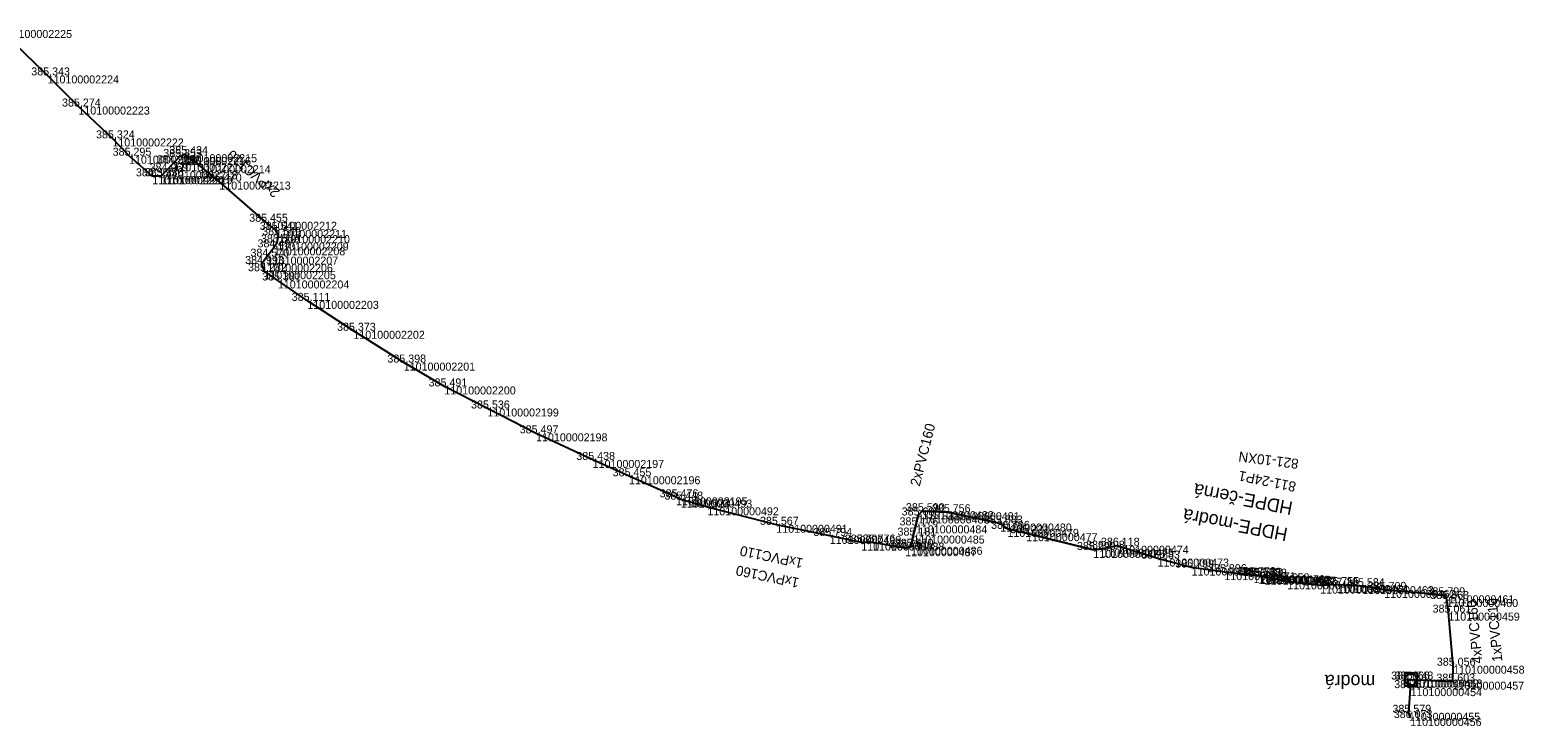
# Model space of a CAD drawing. Extents: x -724084 to -720954, y -948423 to -945131.
# Drawn here: x -721178.5 to -720954.4, y -948422.5 to -948318.1 of the extents above; entities that cross this region are included whole.
import ezdxf

# ---------------------------------------------------------------- set-up
doc = ezdxf.new("R2010")
doc.units = 0
for name, color, linetype in [('Vrstva 28', 7, 'Continuous'), ('Vrstva 31', 7, 'Continuous'), ('Vrstva 33', 7, 'Continuous'), ('Vrstva 35', 7, 'Continuous'), ('Vrstva 60', 7, 'Continuous'), ('Vrstva 61', 7, 'Continuous')]:
    doc.layers.add(name, color=color, linetype=linetype)

msp = doc.modelspace()

# ---------------------------------------------------------------- linework, layer by layer
at = {"layer": 'Vrstva 28'}
for points in [[(-721017.64, -948395.91), (-721019.02, -948396.1), (-721029.09, -948393.58), (-721031.89, -948392.93), (-721032.96, -948392.13), (-721040.78, -948390.44), (-721044.67, -948390.28), (-721045.3, -948390.92), (-721045.63, -948392.41), (-721046.02, -948393.94), (-721046.35, -948395.62), (-721047.24, -948395.83), (-721052.06, -948394.98), (-721053.83, -948394.99), (-721058.55, -948393.99), (-721066.56, -948392.32), (-721076.9, -948389.7), (-721080.89, -948388.54), (-721081.6, -948388.2), (-721088.66, -948385.04), (-721094.11, -948382.59), (-721102.6, -948378.6), (-721109.9, -948374.87), (-721116.36, -948371.56), (-721122.45, -948367.98), (-721130, -948363.21), (-721136.9, -948358.72), (-721141.33, -948355.66), (-721143.35, -948354.27), (-721143.79, -948353.18), (-721142.99, -948352.08), (-721141.93, -948350.69), (-721141.42, -948349.96), (-721141.23, -948348.86), (-721141.68, -948348.07), (-721143.18, -948346.85), (-721150.11, -948340.82), (-721153.11, -948338.36), (-721155.16, -948336.71), (-721156.07, -948337.13), (-721157, -948338.07), (-721158.11, -948339.27), (-721158.84, -948340.01), (-721160.16, -948340.03), (-721163.65, -948336.94), (-721166.15, -948334.34), (-721171.25, -948329.56), (-721175.87, -948324.89), (-721182.91, -948318.07)], [(-720966.59, -948402.9), (-720975.39, -948402.09), (-720978.66, -948401.53), (-720982.49, -948401.35), (-720984.99, -948401.45), (-720989.94, -948400.81), (-720993.33, -948400.12), (-720993.99, -948399.99), (-720994.27, -948399.98), (-720994.99, -948399.88), (-720999.36, -948399.43), (-721004.27, -948398.73), (-721009.38, -948397.39), (-721015.42, -948395.46), (-721017.64, -948395.91)], [(-720965.1, -948415.86), (-720965.04, -948413.47), (-720965.76, -948405.5), (-720966.01, -948403.46), (-720966.59, -948402.9)], [(-720971.49, -948421.32), (-720971.69, -948420.53), (-720971.43, -948416.83), (-720971.89, -948415.54), (-720971.36, -948415.54), (-720965.1, -948415.86)]]:
    msp.add_lwpolyline(points, dxfattribs=at)
at = {"layer": 'Vrstva 31'}
for points in [[(-721017.64, -948395.91), (-721019.02, -948396.1), (-721029.09, -948393.58), (-721031.89, -948392.93), (-721032.96, -948392.13), (-721040.78, -948390.44), (-721044.67, -948390.28), (-721045.3, -948390.92), (-721045.63, -948392.41), (-721046.02, -948393.94), (-721046.35, -948395.62), (-721047.24, -948395.83), (-721052.06, -948394.98), (-721053.83, -948394.99), (-721058.55, -948393.99), (-721066.56, -948392.32), (-721076.9, -948389.7), (-721080.89, -948388.54), (-721081.6, -948388.2), (-721088.66, -948385.04), (-721094.11, -948382.59), (-721102.6, -948378.6), (-721109.9, -948374.87), (-721116.36, -948371.56), (-721122.45, -948367.98), (-721130, -948363.21), (-721136.9, -948358.72), (-721141.33, -948355.66), (-721143.35, -948354.27), (-721143.79, -948353.18), (-721142.99, -948352.08), (-721141.93, -948350.69), (-721141.42, -948349.96), (-721141.23, -948348.86), (-721141.68, -948348.07), (-721143.18, -948346.85), (-721150.11, -948340.82), (-721153.11, -948338.36), (-721155.16, -948336.71), (-721156.07, -948337.13), (-721157, -948338.07), (-721158.11, -948339.27), (-721158.84, -948340.01), (-721160.16, -948340.03), (-721163.65, -948336.94), (-721166.15, -948334.34), (-721171.25, -948329.56), (-721175.87, -948324.89), (-721182.91, -948318.07)], [(-720966.59, -948402.9), (-720975.39, -948402.09), (-720978.66, -948401.53), (-720982.49, -948401.35), (-720984.99, -948401.45), (-720989.94, -948400.81), (-720993.33, -948400.12), (-720993.99, -948399.99), (-720994.27, -948399.98), (-720994.99, -948399.88), (-720999.36, -948399.43), (-721004.27, -948398.73), (-721009.38, -948397.39), (-721015.42, -948395.46), (-721017.64, -948395.91)], [(-720965.1, -948415.86), (-720965.04, -948413.47), (-720965.76, -948405.5), (-720966.01, -948403.46), (-720966.59, -948402.9)], [(-720971.49, -948421.32), (-720971.69, -948420.53), (-720971.43, -948416.83), (-720971.89, -948415.54), (-720971.36, -948415.54), (-720965.1, -948415.86)]]:
    msp.add_lwpolyline(points, dxfattribs=at)
at = {"layer": 'Vrstva 33'}
msp.add_lwpolyline([(-720971.49, -948421.32), (-720971.69, -948420.53), (-720971.43, -948416.83), (-720971.89, -948415.54), (-720971.36, -948415.54), (-720965.1, -948415.86), (-720965.04, -948413.47), (-720965.76, -948405.5), (-720966.01, -948403.46), (-720966.59, -948402.9), (-720975.39, -948402.09), (-720978.66, -948401.53), (-720982.49, -948401.35), (-720984.99, -948401.45), (-720989.94, -948400.81), (-720993.33, -948400.12), (-720993.99, -948399.99), (-720994.27, -948399.98), (-720994.99, -948399.88), (-720999.36, -948399.43), (-721004.27, -948398.73), (-721009.38, -948397.39), (-721015.42, -948395.46), (-721017.64, -948395.91), (-721019.02, -948396.1), (-721029.09, -948393.58), (-721031.89, -948392.93), (-721032.96, -948392.13), (-721040.78, -948390.44), (-721044.67, -948390.28), (-721045.3, -948390.92), (-721045.63, -948392.41), (-721046.02, -948393.94), (-721046.35, -948395.62), (-721047.24, -948395.83), (-721052.06, -948394.98), (-721053.83, -948394.99), (-721058.55, -948393.99), (-721066.56, -948392.32), (-721076.9, -948389.7), (-721080.89, -948388.54), (-721081.6, -948388.2), (-721088.66, -948385.04), (-721094.11, -948382.59), (-721102.6, -948378.6), (-721109.9, -948374.87), (-721116.36, -948371.56), (-721122.45, -948367.98), (-721130, -948363.21), (-721136.9, -948358.72), (-721141.33, -948355.66), (-721143.35, -948354.27), (-721143.79, -948353.18), (-721142.99, -948352.08), (-721141.93, -948350.69), (-721141.42, -948349.96), (-721141.23, -948348.86), (-721141.68, -948348.07), (-721143.18, -948346.85), (-721150.11, -948340.82), (-721153.11, -948338.36), (-721155.16, -948336.71), (-721156.07, -948337.13), (-721157, -948338.07), (-721158.11, -948339.27), (-721158.84, -948340.01), (-721160.16, -948340.03), (-721163.65, -948336.94), (-721166.15, -948334.34), (-721171.25, -948329.56), (-721175.87, -948324.89), (-721182.91, -948318.07)], dxfattribs=at)
msp.add_lwpolyline([(-720970.4, -948414.58), (-720972.32, -948414.58), (-720972.32, -948416.5), (-720970.4, -948416.5)], close=True, dxfattribs=at)
msp.add_circle((-720971.37, -948415.54), 0.864, dxfattribs=at)
at = {"layer": 'Vrstva 35'}
for points in [[(-721143.35, -948354.27), (-721143.79, -948353.18), (-721142.99, -948352.08), (-721141.93, -948350.69), (-721141.42, -948349.96), (-721141.23, -948348.86), (-721141.68, -948348.07), (-721143.18, -948346.85), (-721150.11, -948340.82), (-721153.11, -948338.36), (-721155.16, -948336.71), (-721156.07, -948337.13), (-721157, -948338.07), (-721158.11, -948339.27), (-721158.84, -948340.01), (-721160.16, -948340.03)], [(-721052.06, -948394.98), (-721053.83, -948394.99), (-721058.55, -948393.99), (-721066.56, -948392.32), (-721076.9, -948389.7), (-721080.89, -948388.54)], [(-721047.24, -948395.83), (-721046.35, -948395.62), (-721046.02, -948393.94), (-721045.63, -948392.41), (-721045.3, -948390.92), (-721044.67, -948390.28), (-721040.78, -948390.44), (-721032.96, -948392.13), (-721031.89, -948392.93), (-721029.09, -948393.58), (-721019.02, -948396.1), (-721017.64, -948395.91)], [(-720965.1, -948415.86), (-720965.04, -948413.47), (-720965.76, -948405.5), (-720966.01, -948403.46), (-720966.59, -948402.9)]]:
    msp.add_lwpolyline(points, dxfattribs=at)
at = {"layer": 'Vrstva 60'}
for p, q in [((-721175.87, -948324.89), (-721175.87, -948324.89)), ((-721171.25, -948329.56), (-721171.25, -948329.56)), ((-721166.15, -948334.34), (-721166.15, -948334.34)), ((-721163.65, -948336.94), (-721163.65, -948336.94)), ((-721156.07, -948337.13), (-721156.07, -948337.13)), ((-721155.16, -948336.71), (-721155.16, -948336.71)), ((-721158.11, -948339.27), (-721158.11, -948339.27)), ((-721157, -948338.07), (-721157, -948338.07)), ((-721153.11, -948338.36), (-721153.11, -948338.36)), ((-721160.16, -948340.03), (-721160.16, -948340.03)), ((-721158.84, -948340.01), (-721158.84, -948340.01)), ((-721150.11, -948340.82), (-721150.11, -948340.82)), ((-721143.18, -948346.85), (-721143.18, -948346.85)), ((-721141.68, -948348.07), (-721141.68, -948348.07)), ((-721141.93, -948350.69), (-721141.93, -948350.69)), ((-721141.42, -948349.96), (-721141.42, -948349.96)), ((-721141.23, -948348.86), (-721141.23, -948348.86)), ((-721142.99, -948352.08), (-721142.99, -948352.08)), ((-721143.79, -948353.18), (-721143.79, -948353.18)), ((-721143.35, -948354.27), (-721143.35, -948354.27)), ((-721141.33, -948355.66), (-721141.33, -948355.66)), ((-721136.9, -948358.72), (-721136.9, -948358.72)), ((-721130, -948363.21), (-721130, -948363.21)), ((-721122.45, -948367.98), (-721122.45, -948367.98)), ((-721116.36, -948371.56), (-721116.36, -948371.56)), ((-721109.9, -948374.87), (-721109.9, -948374.87)), ((-721102.6, -948378.6), (-721102.6, -948378.6)), ((-721094.11, -948382.59), (-721094.11, -948382.59)), ((-721088.66, -948385.04), (-721088.66, -948385.04)), ((-721081.6, -948388.2), (-721081.6, -948388.2)), ((-721080.89, -948388.54), (-721080.89, -948388.54)), ((-721076.9, -948389.7), (-721076.9, -948389.7)), ((-721045.3, -948390.92), (-721045.3, -948390.92)), ((-721044.67, -948390.28), (-721044.67, -948390.28)), ((-721040.78, -948390.44), (-721040.78, -948390.44)), ((-721066.56, -948392.32), (-721066.56, -948392.32)), ((-721045.63, -948392.41), (-721045.63, -948392.41)), ((-721032.96, -948392.13), (-721032.96, -948392.13)), ((-721031.89, -948392.93), (-721031.89, -948392.93)), ((-721058.55, -948393.99), (-721058.55, -948393.99)), ((-721053.83, -948394.99), (-721053.83, -948394.99)), ((-721052.06, -948394.98), (-721052.06, -948394.98)), ((-721046.35, -948395.62), (-721046.35, -948395.62)), ((-721046.02, -948393.94), (-721046.02, -948393.94)), ((-721029.09, -948393.58), (-721029.09, -948393.58)), ((-721015.42, -948395.46), (-721015.42, -948395.46)), ((-721047.24, -948395.83), (-721047.24, -948395.83)), ((-721019.02, -948396.1), (-721019.02, -948396.1)), ((-721017.64, -948395.91), (-721017.64, -948395.91)), ((-721009.38, -948397.39), (-721009.38, -948397.39)), ((-721004.27, -948398.73), (-721004.27, -948398.73)), ((-720999.36, -948399.43), (-720999.36, -948399.43)), ((-720994.99, -948399.88), (-720994.99, -948399.88)), ((-720994.27, -948399.98), (-720994.27, -948399.98)), ((-720993.99, -948399.99), (-720993.99, -948399.99)), ((-720993.33, -948400.12), (-720993.33, -948400.12)), ((-720989.94, -948400.81), (-720989.94, -948400.81)), ((-720984.99, -948401.45), (-720984.99, -948401.45)), ((-720982.49, -948401.35), (-720982.49, -948401.35)), ((-720978.66, -948401.53), (-720978.66, -948401.53)), ((-720975.39, -948402.09), (-720975.39, -948402.09)), ((-720966.59, -948402.9), (-720966.59, -948402.9)), ((-720966.01, -948403.46), (-720966.01, -948403.46)), ((-720965.76, -948405.5), (-720965.76, -948405.5)), ((-720965.04, -948413.47), (-720965.04, -948413.47)), ((-720971.89, -948415.54), (-720971.89, -948415.54)), ((-720971.36, -948415.54), (-720971.36, -948415.54)), ((-720971.43, -948416.83), (-720971.43, -948416.83)), ((-720965.1, -948415.86), (-720965.1, -948415.86)), ((-720971.69, -948420.53), (-720971.69, -948420.53)), ((-720971.49, -948421.32), (-720971.49, -948421.32))]:
    msp.add_line(p, q, dxfattribs=at)

# ---------------------------------------------------------------- texts
at = {"layer": 'Vrstva 28'}
msp.add_text('811-24P1', height=1.5, rotation=168.4498, dxfattribs=at).set_placement((-720988.52, -948385.94))
at = {"layer": 'Vrstva 31'}
msp.add_text('821-10XN', height=1.5, rotation=172.6697, dxfattribs=at).set_placement((-720988.16, -948382.47))
at = {"layer": 'Vrstva 33'}
for s, rotation, p in [('HDPE-černá', 169.188, (-720988.99, -948388.91)), ('HDPE-modrá', 169.188, (-720989.74, -948392.84)), ('modrá', 180, (-720976.72, -948414.84))]:
    msp.add_text(s, height=2, rotation=rotation, dxfattribs=at).set_placement(p)
at = {"layer": 'Vrstva 35'}
for s, rotation, p in [('2xPVC110', 138.9782, (-721140.91, -948342.24)), ('2xPVC160', 75.7968, (-721045.06, -948386.64)), ('1xPVC110', 168.2091, (-721062.44, -948397.41)), ('1xPVC160', 168.2091, (-721063.05, -948400.35)), ('4xPVC160', 95.1899, (-720960.64, -948413.09)), ('1xPVC110', 95.1899, (-720957.65, -948412.82))]:
    msp.add_text(s, height=1.5, rotation=rotation, dxfattribs=at).set_placement(p)
at = {"layer": 'Vrstva 60'}
for s, p in [('110100002225', (-721182.91, -948319.27)), ('110100002224', (-721175.87, -948326.09)), ('110100002223', (-721171.25, -948330.76)), ('110100002222', (-721166.15, -948335.55)), ('110100002221', (-721163.65, -948338.14)), ('110100002216', (-721156.07, -948338.33)), ('110100002215', (-721155.16, -948337.91)), ('110100002218', (-721158.11, -948340.47)), ('110100002217', (-721157, -948339.27)), ('110100002214', (-721153.11, -948339.56)), ('110100002220', (-721160.16, -948341.23)), ('110100002219', (-721158.84, -948341.21)), ('110100002213', (-721150.11, -948342.02)), ('110100002212', (-721143.18, -948348.05)), ('110100002211', (-721141.68, -948349.27)), ('110100002208', (-721141.93, -948351.89)), ('110100002209', (-721141.42, -948351.16)), ('110100002210', (-721141.23, -948350.06)), ('110100002207', (-721142.99, -948353.28)), ('110100002206', (-721143.79, -948354.38)), ('110100002205', (-721143.35, -948355.47)), ('110100002204', (-721141.33, -948356.86)), ('110100002203', (-721136.9, -948359.92)), ('110100002202', (-721130, -948364.41)), ('110100002201', (-721122.45, -948369.19)), ('110100002200', (-721116.36, -948372.76)), ('110100002199', (-721109.9, -948376.07)), ('110100002198', (-721102.6, -948379.8)), ('110100002197', (-721094.11, -948383.79)), ('110100002196', (-721088.66, -948386.24)), ('110100002195', (-721081.6, -948389.4)), ('110100000493', (-721080.89, -948389.74)), ('110100000492', (-721076.9, -948390.9)), ('110100000483', (-721045.3, -948392.12)), ('110100000482', (-721044.67, -948391.48)), ('110100000481', (-721040.78, -948391.64)), ('110100000491', (-721066.56, -948393.52)), ('110100000484', (-721045.63, -948393.61)), ('110100000480', (-721032.96, -948393.33)), ('110100000479', (-721031.89, -948394.13)), ('110100000490', (-721058.55, -948395.19)), ('110100000489', (-721053.83, -948396.19)), ('110100000488', (-721052.06, -948396.18)), ('110100000486', (-721046.35, -948396.82)), ('110100000485', (-721046.02, -948395.14)), ('110100000477', (-721029.09, -948394.78)), ('110100000474', (-721015.42, -948396.66)), ('110100000487', (-721047.24, -948397.03)), ('110100000476', (-721019.02, -948397.3)), ('110100000475', (-721017.64, -948397.11)), ('110100000473', (-721009.38, -948398.59)), ('110100000472', (-721004.27, -948399.93)), ('110100000471', (-720999.36, -948400.63)), ('110100000470', (-720994.99, -948401.08)), ('110100000469', (-720994.27, -948401.18)), ('110100000468', (-720993.99, -948401.19)), ('110100000467', (-720993.33, -948401.32)), ('110100000466', (-720989.94, -948402.01)), ('110100000465', (-720984.99, -948402.65)), ('110100000464', (-720982.49, -948402.55)), ('110100000463', (-720978.66, -948402.73)), ('110100000462', (-720975.39, -948403.29)), ('110100000461', (-720966.59, -948404.1)), ('110100000460', (-720966.01, -948404.66)), ('110100000459', (-720965.76, -948406.7)), ('110100000458', (-720965.04, -948414.67)), ('110100000452', (-720971.89, -948416.74)), ('110100000453', (-720971.36, -948416.74)), ('110100000454', (-720971.43, -948418.03)), ('110100000457', (-720965.1, -948417.06)), ('110100000455', (-720971.69, -948421.73)), ('110100000456', (-720971.49, -948422.52))]:
    msp.add_text(s, height=1.2, dxfattribs=at).set_placement(p)
at = {"layer": 'Vrstva 61'}
for s, p in [('385.343', (-721178.32, -948324.89)), ('385.274', (-721173.7, -948329.56)), ('385.324', (-721168.6, -948334.34)), ('385.295', (-721166.11, -948336.94)), ('384.968', (-721159.46, -948338.07)), ('385.353', (-721158.52, -948337.13)), ('385.434', (-721157.61, -948336.71)), ('385.398', (-721155.56, -948338.36)), ('385.355', (-721162.62, -948340.03)), ('385.330', (-721161.29, -948340.01)), ('384.969', (-721160.56, -948339.27)), ('385.470', (-721152.56, -948340.82)), ('385.455', (-721145.63, -948346.85)), ('385.541', (-721144.04, -948348.07)), ('385.549', (-721143.69, -948348.86)), ('384.497', (-721144.38, -948350.69)), ('385.509', (-721143.87, -948349.96)), ('384.993', (-721146.24, -948353.18)), ('384.570', (-721145.44, -948352.08)), ('385.282', (-721145.8, -948354.27)), ('385.381', (-721143.69, -948355.66)), ('385.111', (-721139.25, -948358.72)), ('385.373', (-721132.45, -948363.21)), ('385.398', (-721124.9, -948367.98)), ('385.491', (-721118.72, -948371.56)), ('385.536', (-721112.35, -948374.87)), ('385.497', (-721105.05, -948378.6)), ('385.438', (-721096.56, -948382.59)), ('385.455', (-721091.11, -948385.04)), ('385.476', (-721084.06, -948388.2)), ('385.448', (-721083.34, -948388.54)), ('385.523', (-721079.35, -948389.7)), ('385.567', (-721069.01, -948392.32)), ('385.688', (-721047.76, -948390.92)), ('385.590', (-721047.12, -948390.28)), ('385.756', (-721043.23, -948390.44)), ('385.883', (-721035.41, -948392.13)), ('385.794', (-721061, -948393.99)), ('385.181', (-721048.38, -948393.94)), ('385.176', (-721048.08, -948392.41)), ('385.706', (-721034.35, -948392.93)), ('385.231', (-721031.45, -948393.58)), ('385.795', (-721056.29, -948394.99)), ('385.776', (-721054.51, -948394.98)), ('385.761', (-721049.59, -948395.83)), ('385.570', (-721048.8, -948395.62)), ('385.290', (-721021.47, -948396.1)), ('386.198', (-721020.1, -948395.91)), ('386.118', (-721017.87, -948395.46)), ('385.883', (-721011.83, -948397.39)), ('385.799', (-721006.72, -948398.73)), ('385.806', (-721001.81, -948399.43)), ('385.773', (-720997.44, -948399.88)), ('385.588', (-720996.72, -948399.98)), ('385.583', (-720996.44, -948399.99)), ('385.738', (-720995.78, -948400.12)), ('385.658', (-720992.39, -948400.81)), ('385.737', (-720987.44, -948401.45)), ('385.755', (-720984.94, -948401.35)), ('385.584', (-720981.11, -948401.53)), ('385.709', (-720977.85, -948402.09)), ('385.799', (-720969.04, -948402.9)), ('385.868', (-720968.47, -948403.46)), ('385.061', (-720968.12, -948405.5)), ('385.056', (-720967.49, -948413.47)), ('385.666', (-720974.34, -948415.54)), ('385.670', (-720973.88, -948416.83)), ('385.748', (-720973.82, -948415.54)), ('385.603', (-720967.55, -948415.86)), ('385.579', (-720974.14, -948420.53)), ('386.073', (-720973.95, -948421.32))]:
    msp.add_text(s, height=1.2, dxfattribs=at).set_placement(p)

doc.saveas('drawing.dxf')
